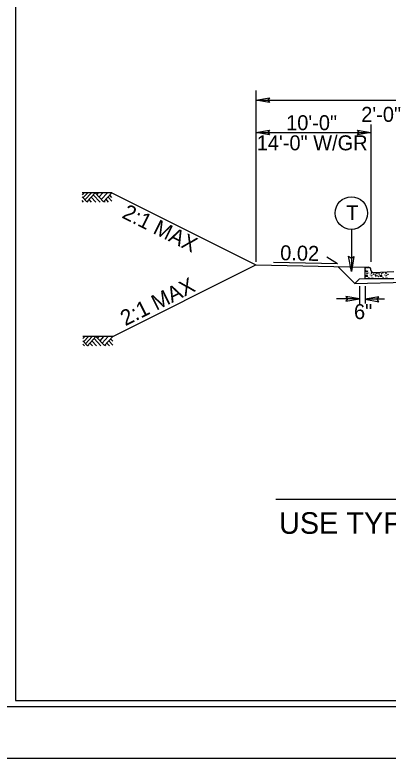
# Model space of a CAD drawing. Extents: x 1904401 to 1905163, y 193929 to 194736.
# Drawn here: x 1904744 to 1904776.5, y 194494.2 to 194558.8 of the extents above; entities that cross this region are included whole.
import ezdxf

# ---------------------------------------------------------------- set-up
doc = ezdxf.new("R2010")
doc.units = 0
for name, color, linetype in [('Old_Level_1', 7, 'Continuous'), ('Old_Level_11', 7, 'Continuous'), ('Old_Level_20', 7, 'Continuous'), ('Prop Dimension Text', 7, 'Continuous'), ('Prop Lane Arrow CELL', 7, 'Continuous'), ('Sheet Cutting Line CELL', 7, 'Continuous'), ('Sheet Plot Border Inside CELL', 7, 'Continuous'), ('Sheet Plot Border Outside CELL', 7, 'Continuous'), ('Sheet Typical CELL', 7, 'Continuous'), ('Typical Arrow Superelevation CELL', 7, 'Continuous'), ('Typical Berm CELL', 7, 'Continuous'), ('Typical Curb CELL', 7, 'Continuous'), ('Typical Hinge Slope Arterial CELL', 7, 'Continuous'), ('Typical Pavement Slope CELL', 7, 'Continuous'), ('Typical Terminator CELL', 7, 'Continuous')]:
    doc.layers.add(name, color=color, linetype=linetype)

msp = doc.modelspace()

# ---------------------------------------------------------------- linework, layer by layer
at = {"layer": 'Old_Level_1'}
for p, q in [((1904765, 194551.344), (1904828.5, 194551.344)), ((1904765, 194548.532), (1904775, 194548.532)), ((1904750.05, 194543.3), (1904749.88, 194543.117)), ((1904750.37, 194543.3), (1904749.956, 194542.856)), ((1904750.703, 194543.3), (1904750.123, 194542.677)), ((1904751.025, 194543.299), (1904750.284, 194542.503)), ((1904751.446, 194542.495), (1904750.86, 194543.123)), ((1904751.757, 194542.513), (1904751.025, 194543.299)), ((1904751.29, 194543.3), (1904751.156, 194543.157)), ((1904751.691, 194543.3), (1904751.358, 194542.941)), ((1904752.089, 194543.3), (1904751.556, 194542.727)), ((1904752.481, 194543.292), (1904751.757, 194542.513)), ((1904752.481, 194542.891), (1904752.295, 194543.091)), ((1904750.284, 194542.503), (1904749.88, 194542.938)), ((1904750.014, 194542.495), (1904749.88, 194542.638)), ((1904750.416, 194542.495), (1904750.346, 194542.569)), ((1904750.71, 194542.495), (1904750.493, 194542.728)), ((1904751.076, 194542.495), (1904750.676, 194542.924)), ((1904751.882, 194542.495), (1904751.81, 194542.571)), ((1904752.192, 194542.495), (1904751.966, 194542.738)), ((1904752.481, 194542.558), (1904752.138, 194542.924)), ((1904750.118, 194530.814), (1904749.948, 194530.631)), ((1904750.438, 194530.814), (1904750.024, 194530.37)), ((1904750.771, 194530.814), (1904750.191, 194530.191)), ((1904751.093, 194530.813), (1904750.352, 194530.017)), ((1904751.824, 194530.027), (1904751.093, 194530.813)), ((1904751.357, 194530.814), (1904751.224, 194530.671)), ((1904751.759, 194530.814), (1904751.426, 194530.455)), ((1904752.157, 194530.814), (1904751.624, 194530.241)), ((1904752.548, 194530.806), (1904751.824, 194530.027)), ((1904750.352, 194530.017), (1904749.948, 194530.452)), ((1904750.082, 194530.009), (1904749.948, 194530.152)), ((1904750.778, 194530.009), (1904750.561, 194530.242)), ((1904751.144, 194530.009), (1904750.744, 194530.438)), ((1904751.514, 194530.009), (1904750.928, 194530.637)), ((1904752.26, 194530.009), (1904752.033, 194530.252)), ((1904752.548, 194530.072), (1904752.206, 194530.438)), ((1904752.548, 194530.405), (1904752.362, 194530.605)), ((1904750.483, 194530.009), (1904750.414, 194530.083)), ((1904751.949, 194530.009), (1904751.878, 194530.085)), ((1904766.738, 194516.676), (1904819.131, 194516.676))]:
    msp.add_line(p, q, dxfattribs=at)
for points in [[(1904752.481, 194543.3), (1904749.88, 194543.3)], [(1904752.548, 194530.814), (1904749.948, 194530.814)]]:
    msp.add_lwpolyline(points, dxfattribs=at)
at = {"layer": 'Old_Level_11'}
msp.add_line((1904773.296, 194540.124), (1904773.296, 194536.47), dxfattribs=at)
msp.add_lwpolyline([(1904773.522, 194537.779), (1904773.296, 194536.47), (1904773.063, 194537.786), (1904773.296, 194537.619)], close=True, dxfattribs=at)
msp.add_circle((1904773.296, 194541.538), 1.414, dxfattribs=at)
at = {"layer": 'Prop Dimension Text'}
for p, q in [((1904765, 194552.172), (1904765, 194537.306)), ((1904775, 194549.225), (1904775, 194537.306))]:
    msp.add_line(p, q, dxfattribs=at)
at = {"layer": 'Prop Lane Arrow CELL'}
for p, q in [((1904774.001, 194535.192), (1904774.001, 194533.653)), ((1904774.501, 194535.191), (1904774.501, 194533.693)), ((1904774.001, 194534.075), (1904772.011, 194534.075)), ((1904776.173, 194534.047), (1904774.501, 194534.047))]:
    msp.add_line(p, q, dxfattribs=at)
at = {"layer": 'Sheet Cutting Line CELL'}
msp.add_line((1904710.692, 194494.195), (1905047.492, 194494.195), dxfattribs=at)
at = {"layer": 'Sheet Plot Border Inside CELL'}
msp.add_lwpolyline([(1905046.592, 194709.705), (1904713.292, 194709.705), (1904713.292, 194498.685), (1905046.592, 194498.685)], close=True, dxfattribs=at)
at = {"layer": 'Sheet Plot Border Outside CELL'}
msp.add_lwpolyline([(1905047.492, 194714.195), (1904710.692, 194714.195), (1904710.692, 194494.195), (1905047.492, 194494.195)], close=True, dxfattribs=at)
at = {"layer": 'Sheet Typical CELL'}
msp.add_line((1904744.092, 194499.195), (1904744.092, 194499.195), dxfattribs=at)
msp.add_line((1904744.092, 194499.195), (1904744.092, 194499.195), dxfattribs=at)
msp.add_line((1904744.092, 194499.195), (1904744.092, 194499.195), dxfattribs=at)
msp.add_line((1904744.092, 194499.195), (1904744.092, 194499.195), dxfattribs=at)
msp.add_line((1904744.092, 194499.195), (1904744.092, 194499.195), dxfattribs=at)
msp.add_line((1904744.092, 194499.195), (1904744.092, 194499.195), dxfattribs=at)
msp.add_lwpolyline([(1905044.092, 194709.195), (1904744.092, 194709.195), (1904744.092, 194499.195), (1905044.092, 194499.195)], close=True, dxfattribs=at)
msp.add_lwpolyline([(1904751.592, 194499.195), (1904751.592, 194499.195)], dxfattribs=at)
at = {"layer": 'Typical Arrow Superelevation CELL'}
for q in [(1904766.514, 194537.249), (1904771.167, 194537.705)]:
    msp.add_line((1904772.107, 194537.137), q, dxfattribs=at)
at = {"layer": 'Typical Berm CELL'}
msp.add_line((1904765, 194537.04), (1904774.501, 194536.842), dxfattribs=at)
at = {"layer": 'Typical Curb CELL'}
for p, q in [((1904774.501, 194535.842), (1904774.501, 194536.842)), ((1904774.501, 194536.842), (1904774.761, 194536.842)), ((1904775.001, 194536.592), (1904775.001, 194536.603)), ((1904774.537, 194536.464), (1904774.691, 194536.509)), ((1904774.675, 194536.418), (1904774.537, 194536.464)), ((1904774.663, 194536.145), (1904774.56, 194536.07)), ((1904774.56, 194536.07), (1904774.726, 194536.031)), ((1904774.726, 194536.031), (1904774.663, 194536.145)), ((1904774.691, 194536.509), (1904774.675, 194536.418)), ((1904777, 194536.426), (1904775.25, 194536.353)), ((1904775.405, 194536.202), (1904775.371, 194536.088)), ((1904775.371, 194536.088), (1904775.49, 194536.082)), ((1904775.49, 194536.082), (1904775.405, 194536.202)), ((1904775.912, 194536.145), (1904775.809, 194536.07)), ((1904775.809, 194536.07), (1904775.975, 194536.031)), ((1904775.975, 194536.031), (1904775.912, 194536.145)), ((1904774.501, 194535.842), (1904777, 194535.842))]:
    msp.add_line(p, q, dxfattribs=at)
for centre in [(1904774.514, 194536.732), (1904774.731, 194536.766), (1904774.566, 194536.549), (1904774.663, 194536.276), (1904774.783, 194536.327), (1904774.817, 194535.928), (1904774.96, 194536.162), (1904775.04, 194536.355), (1904775.051, 194535.98), (1904775.057, 194536.305), (1904775.085, 194536.134), (1904775.234, 194536.219), (1904775.262, 194536.321), (1904775.456, 194536.282), (1904775.553, 194536.336), (1904775.582, 194536.082), (1904775.662, 194536.242), (1904775.678, 194536.037), (1904775.718, 194536.276), (1904775.735, 194536.179), (1904775.912, 194536.276), (1904776.032, 194536.327), (1904776.066, 194535.928), (1904776.209, 194536.162), (1904776.289, 194536.355), (1904776.3, 194535.98), (1904776.306, 194536.305), (1904776.334, 194536.134), (1904776.483, 194536.219), (1904774.646, 194535.888), (1904774.994, 194535.865), (1904775.165, 194535.894), (1904775.371, 194535.917), (1904775.53, 194535.848), (1904775.741, 194535.871), (1904775.895, 194535.888), (1904776.243, 194535.865), (1904776.414, 194535.894)]:
    msp.add_circle(centre, 0.00802, dxfattribs=at)
for centre, start, end in [((1904774.761, 194536.603), 0, 90), ((1904775.24, 194536.592), 180, 272.38446)]:
    msp.add_arc(centre, 0.24, start, end, dxfattribs=at)
at = {"layer": 'Typical Hinge Slope Arterial CELL'}
for p in [(1904752.481, 194543.3), (1904752.548, 194530.814)]:
    msp.add_line(p, (1904765, 194537.04), dxfattribs=at)
at = {"layer": 'Typical Pavement Slope CELL'}
for p, q in [((1904773.597, 194535.429), (1904772.134, 194536.891)), ((1904773.597, 194535.429), (1904796.75, 194535.974)), ((1904773.597, 194535.429), (1904774.001, 194535.832)), ((1904774.001, 194535.832), (1904774.501, 194535.842))]:
    msp.add_line(p, q, dxfattribs=at)
at = {"layer": 'Typical Terminator CELL'}
for points in [[(1904766.172, 194551.143), (1904765, 194551.344), (1904766.179, 194551.553), (1904766.029, 194551.344)], [(1904766.172, 194548.33), (1904765, 194548.532), (1904766.179, 194548.74), (1904766.029, 194548.532)], [(1904773.829, 194548.734), (1904775, 194548.532), (1904773.822, 194548.324), (1904773.972, 194548.532)], [(1904772.829, 194533.873), (1904774.001, 194534.075), (1904772.823, 194534.283), (1904772.973, 194534.075)], [(1904775.673, 194534.249), (1904774.501, 194534.047), (1904775.679, 194533.839), (1904775.529, 194534.047)]]:
    msp.add_lwpolyline(points, close=True, dxfattribs=at)

# ---------------------------------------------------------------- texts
at = {"layer": 'Old_Level_1'}
for s, p in [('2\'-0"', (1904774.159, 194549.462)), ('10\'-0" ', (1904767.627, 194548.738)), ('14\'-0" W/GR', (1904765.07, 194546.988))]:
    msp.add_text(s, height=1.3, dxfattribs=at).set_placement(p)
at = {"layer": 'Old_Level_20'}
msp.add_text('T', height=1.279, dxfattribs=at).set_placement((1904772.86, 194540.941))
at = {"layer": 'Prop Dimension Text'}
msp.add_text('0.02', height=1.3, rotation=358.8538, dxfattribs=at).set_placement((1904767.1, 194537.445))
at = {"layer": 'Prop Lane Arrow CELL'}
msp.add_text('6"', height=1.3, rotation=0.00016, dxfattribs=at).set_placement((1904773.529, 194532.328))
msp.add_text('USE TYPICAL SECTION NO. 3', height=1.875, dxfattribs=at).set_placement((1904767.01, 194513.679))
at = {"layer": 'Typical Hinge Slope Arterial CELL'}
for rotation, p in [(333.43495, (1904753.272, 194541.162)), (26.56505, (1904753.644, 194531.703))]:
    msp.add_text('2:1 MAX', height=1.35, rotation=rotation, dxfattribs=at).set_placement(p)

doc.saveas('drawing.dxf')
